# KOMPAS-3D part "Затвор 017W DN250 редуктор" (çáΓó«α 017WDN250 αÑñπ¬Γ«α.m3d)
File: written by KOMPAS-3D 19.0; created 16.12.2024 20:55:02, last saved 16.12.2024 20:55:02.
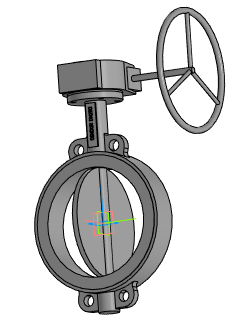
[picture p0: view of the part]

Document properties: Автор: Евгений; Полное имя файла: ..\Затвор 017WDN250 редуктор.a3d

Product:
- Part/product: Затвор 017W DN250 редуктор
    Масса: 39.3806

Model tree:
1. Операция без истории:1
